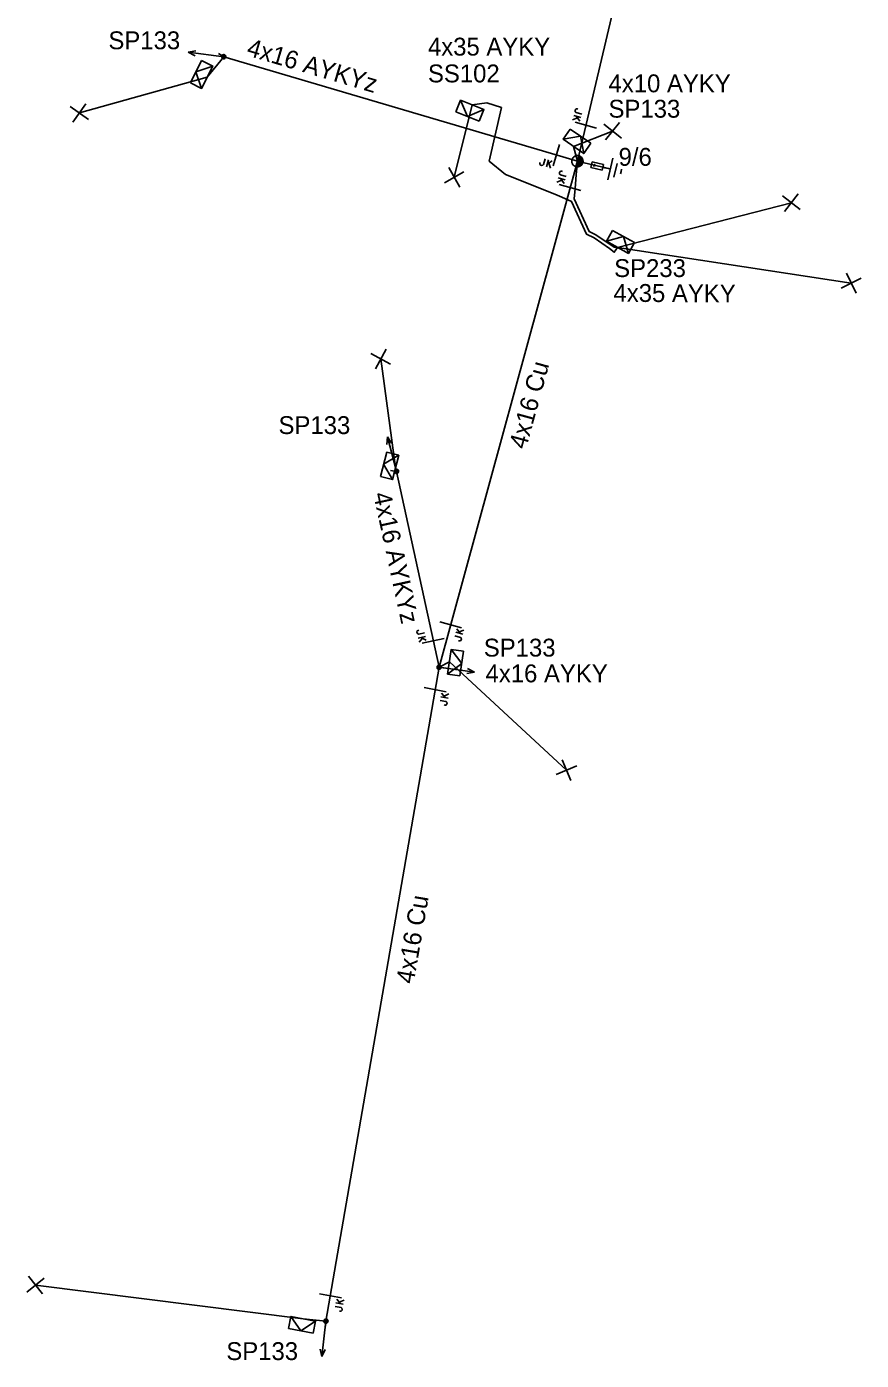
# Model space of a CAD drawing. Extents: x -788458 to -786145, y -1154772 to -1152372.
# Drawn here: x -786448.1 to -786401.4, y -1153622.8 to -1153548.2 of the extents above; entities that cross this region are included whole.
import ezdxf

# ---------------------------------------------------------------- set-up
doc = ezdxf.new("R2010")
doc.units = 0
for name, color, linetype in [('Vrstva 1', 7, 'Continuous'), ('Vrstva 12', 7, 'Continuous'), ('Vrstva 13', 7, 'Continuous'), ('Vrstva 14', 7, 'Continuous'), ('Vrstva 15', 7, 'Continuous'), ('Vrstva 16', 7, 'Continuous'), ('Vrstva 18', 7, 'Continuous'), ('Vrstva 2', 7, 'Continuous'), ('Vrstva 31', 7, 'Continuous'), ('Vrstva 33', 7, 'Continuous'), ('Vrstva 34', 7, 'Continuous'), ('Vrstva 4', 7, 'Continuous'), ('Vrstva 5', 7, 'Continuous'), ('Vrstva 52', 7, 'Continuous'), ('Vrstva 53', 7, 'Continuous'), ('Vrstva 54', 7, 'Continuous'), ('Vrstva 55', 7, 'Continuous'), ('Vrstva 59', 7, 'Continuous'), ('Vrstva 6', 7, 'Continuous'), ('Vrstva 9', 7, 'Continuous')]:
    doc.layers.add(name, color=color, linetype=linetype)

# ---------------------------------------------------------------- blocks, each defined once
blk = doc.blocks.new('NN440')
at = {"layer": 'Vrstva 2'}
for points in [[(0.63, 0), (0.63, 0.06), (0.62, 0.13), (0.6, 0.19), (0.58, 0.25), (0.55, 0.31), (0.51, 0.37), (0.47, 0.42), (0.42, 0.46), (0.37, 0.51), (0.32, 0.54), (0.26, 0.57), (0.2, 0.59), (0.13, 0.61), (0.07, 0.62), (0, 0.63), (-0.06, 0.62), (-0.13, 0.61), (-0.19, 0.59), (-0.26, 0.57), (-0.31, 0.54), (-0.37, 0.51), (-0.42, 0.46), (-0.47, 0.42), (-0.51, 0.37), (-0.54, 0.31), (-0.57, 0.25), (-0.6, 0.19), (-0.62, 0.13), (-0.63, 0.06), (-0.63, 0), (-0.63, -0.07), (-0.62, -0.14), (-0.6, -0.2), (-0.57, -0.26), (-0.54, -0.32), (-0.51, -0.37), (-0.47, -0.43), (-0.42, -0.47), (-0.37, -0.51), (-0.31, -0.55), (-0.26, -0.58), (-0.19, -0.6), (-0.13, -0.62), (-0.06, -0.63), (0, -0.63), (0.07, -0.63), (0.13, -0.62), (0.2, -0.6), (0.26, -0.58), (0.32, -0.55), (0.37, -0.51), (0.42, -0.47), (0.47, -0.43), (0.51, -0.37), (0.55, -0.32), (0.58, -0.26), (0.6, -0.2), (0.62, -0.14), (0.63, -0.07), (0.63, 0)], [(-0.63, 0), (0.63, 0)], [(-0.6, -0.18), (0.57, -0.18)], [(-0.51, -0.32), (0.5, -0.32)], [(-0.37, -0.47), (0.35, -0.47)]]:
    blk.add_lwpolyline(points, dxfattribs=at)
blk = doc.blocks.new('NN560')
at = {"layer": 'Vrstva 2'}
for points in [[(1.999, -0.001), (1.59, 0.141)], [(0, -0.001), (1.999, -0.001)], [(1.999, -0.001), (1.59, -0.134)]]:
    blk.add_lwpolyline(points, dxfattribs=at)
blk = doc.blocks.new('NN840')
at = {"layer": 'Vrstva 15'}
for points in [[(0.003, 0.619), (0.003, -0.631)], [(-0.745, -0.71), (-0.745, -0.66)], [(-0.73, -0.764), (-0.745, -0.71)], [(-0.538, -0.71), (-0.558, -0.764)], [(-0.538, -0.385), (-0.538, -0.71)], [(-0.332, -0.385), (-0.332, -0.798)], [(-0.332, -0.641), (-0.125, -0.385)], [(-0.263, -0.557), (-0.091, -0.798)], [(-0.657, -0.798), (-0.73, -0.764)], [(-0.627, -0.798), (-0.657, -0.798)], [(-0.558, -0.764), (-0.627, -0.798)]]:
    blk.add_lwpolyline(points, dxfattribs=at)
blk = doc.blocks.new('NN800')
at = {"layer": 'Vrstva 1'}
for points in [[(-0.442, 0.442), (0.442, -0.442)], [(-0.442, -0.442), (0.442, 0.442)]]:
    blk.add_lwpolyline(points, dxfattribs=at)
blk = doc.blocks.new('NN820')
at = {"layer": 'Vrstva 13'}
for points in [[(-0.003, 0.004), (-0.003, -1.049)], [(-0.165, -0.813), (0.165, -0.813)], [(-0.165, -1.473), (-0.165, -0.813)], [(0.165, -1.473), (-0.165, -1.473)], [(-0.003, -1.049), (-0.062, -0.926)], [(-0.003, -1.049), (0.057, -0.926)], [(-0.003, -1.473), (-0.003, -1.871)], [(0.165, -0.813), (0.165, -1.473)]]:
    blk.add_lwpolyline(points, dxfattribs=at)
blk = doc.blocks.new('NN630')
at = {"layer": 'Vrstva 9'}
for points in [[(-0.003, -0.7), (-0.703, 0)], [(-0.703, -0.7), (-0.703, 0), (0.697, 0), (0.697, -0.7)], [(-0.703, -0.7), (0.697, -0.7)], [(-0.003, -0.7), (0.697, 0)]]:
    blk.add_lwpolyline(points, dxfattribs=at)
blk = doc.blocks.new('NN810')
at = {"layer": 'Vrstva 14'}
for points in [[(0.004, -0.64), (0.004, -1.89)], [(0.629, -1.89), (-0.621, -1.89)], [(0.388, -2.2), (-0.399, -2.2)], [(0.004, -2.515), (-0.124, -2.515)], [(0.137, -2.515), (0.004, -2.515)]]:
    blk.add_lwpolyline(points, dxfattribs=at)
blk = doc.blocks.new('NN500')
at = {"layer": 'Vrstva 2'}
for points in [[(0, -0.24), (0.02, -0.23), (0.05, -0.23), (0.07, -0.22), (0.09, -0.22), (0.12, -0.2), (0.14, -0.19), (0.16, -0.18), (0.17, -0.16), (0.19, -0.14), (0.2, -0.12), (0.21, -0.1), (0.22, -0.07), (0.23, -0.05), (0.23, -0.02), (0.23, 0), (0.23, 0.02), (0.23, 0.05), (0.22, 0.07), (0.21, 0.1), (0.2, 0.12), (0.19, 0.14), (0.17, 0.16), (0.16, 0.17), (0.14, 0.19), (0.12, 0.2), (0.09, 0.21), (0.07, 0.22), (0.05, 0.23), (0.02, 0.23), (0, 0.23), (-0.03, 0.23), (-0.05, 0.23), (-0.07, 0.22), (-0.1, 0.21), (-0.12, 0.2), (-0.14, 0.19), (-0.16, 0.17), (-0.18, 0.16), (-0.19, 0.14), (-0.2, 0.12), (-0.22, 0.1), (-0.22, 0.07), (-0.23, 0.05), (-0.23, 0.02), (-0.24, 0), (-0.23, -0.02), (-0.23, -0.05), (-0.22, -0.07), (-0.22, -0.1), (-0.2, -0.12), (-0.19, -0.14), (-0.18, -0.16), (-0.16, -0.18), (-0.14, -0.19), (-0.12, -0.2), (-0.1, -0.22), (-0.07, -0.22), (-0.05, -0.23), (-0.03, -0.23), (0, -0.24)], [(0, -0.24), (0.02, -0.23), (0.05, -0.23), (0.07, -0.22), (0.09, -0.22), (0.12, -0.2), (0.14, -0.19), (0.16, -0.18), (0.17, -0.16), (0.19, -0.14), (0.2, -0.12), (0.21, -0.1), (0.22, -0.07), (0.23, -0.05), (0.23, -0.02), (0.23, 0), (0.23, 0.02), (0.23, 0.05), (0.22, 0.07), (0.21, 0.1), (0.2, 0.12), (0.19, 0.14), (0.17, 0.16), (0.16, 0.17), (0.14, 0.19), (0.12, 0.2), (0.09, 0.21), (0.07, 0.22), (0.05, 0.23), (0.02, 0.23), (0, 0.23), (-0.03, 0.23), (-0.05, 0.23), (-0.07, 0.22), (-0.1, 0.21), (-0.12, 0.2), (-0.14, 0.19), (-0.16, 0.17), (-0.18, 0.16), (-0.19, 0.14), (-0.2, 0.12), (-0.22, 0.1), (-0.22, 0.07), (-0.23, 0.05), (-0.23, 0.02), (-0.24, 0), (-0.23, -0.02), (-0.23, -0.05), (-0.22, -0.07), (-0.22, -0.1), (-0.2, -0.12), (-0.19, -0.14), (-0.18, -0.16), (-0.16, -0.18), (-0.14, -0.19), (-0.12, -0.2), (-0.1, -0.22), (-0.07, -0.22), (-0.05, -0.23), (-0.03, -0.23), (0, -0.24)], [(0, -0.21), (0.02, -0.2), (0.04, -0.2), (0.06, -0.2), (0.08, -0.19), (0.1, -0.18), (0.12, -0.17), (0.14, -0.15), (0.15, -0.14), (0.16, -0.12), (0.18, -0.1), (0.19, -0.08), (0.19, -0.06), (0.2, -0.04), (0.2, -0.02), (0.2, 0), (0.2, 0.02), (0.2, 0.04), (0.19, 0.06), (0.19, 0.08), (0.18, 0.1), (0.16, 0.12), (0.15, 0.14), (0.14, 0.15), (0.12, 0.17), (0.1, 0.18), (0.08, 0.19), (0.06, 0.19), (0.04, 0.2), (0.02, 0.2), (0, 0.2), (-0.02, 0.2), (-0.04, 0.2), (-0.06, 0.19), (-0.08, 0.19), (-0.1, 0.18), (-0.12, 0.17), (-0.14, 0.15), (-0.15, 0.14), (-0.17, 0.12), (-0.18, 0.1), (-0.19, 0.08), (-0.2, 0.06), (-0.2, 0.04), (-0.21, 0.02), (-0.21, 0), (-0.21, -0.02), (-0.2, -0.04), (-0.2, -0.06), (-0.19, -0.08), (-0.18, -0.1), (-0.17, -0.12), (-0.15, -0.14), (-0.14, -0.15), (-0.12, -0.17), (-0.1, -0.18), (-0.08, -0.19), (-0.06, -0.2), (-0.04, -0.2), (-0.02, -0.2), (0, -0.21)], [(0, -0.18), (0.02, -0.18), (0.04, -0.17), (0.05, -0.17), (0.07, -0.16), (0.09, -0.15), (0.1, -0.14), (0.12, -0.13), (0.13, -0.12), (0.14, -0.1), (0.15, -0.09), (0.16, -0.07), (0.17, -0.05), (0.17, -0.04), (0.17, -0.02), (0.17, 0), (0.17, 0.02), (0.17, 0.04), (0.17, 0.05), (0.16, 0.07), (0.15, 0.09), (0.14, 0.1), (0.13, 0.12), (0.12, 0.13), (0.1, 0.14), (0.09, 0.15), (0.07, 0.16), (0.05, 0.17), (0.04, 0.17), (0.02, 0.17), (0, 0.18), (-0.02, 0.17), (-0.04, 0.17), (-0.06, 0.17), (-0.07, 0.16), (-0.09, 0.15), (-0.1, 0.14), (-0.12, 0.13), (-0.13, 0.12), (-0.14, 0.1), (-0.15, 0.09), (-0.16, 0.07), (-0.17, 0.05), (-0.17, 0.04), (-0.18, 0.02), (-0.18, 0), (-0.18, -0.02), (-0.17, -0.04), (-0.17, -0.05), (-0.16, -0.07), (-0.15, -0.09), (-0.14, -0.1), (-0.13, -0.12), (-0.12, -0.13), (-0.1, -0.14), (-0.09, -0.15), (-0.07, -0.16), (-0.06, -0.17), (-0.04, -0.17), (-0.02, -0.18), (0, -0.18)], [(0, -0.15), (0.01, -0.15), (0.03, -0.14), (0.04, -0.14), (0.06, -0.13), (0.07, -0.13), (0.08, -0.12), (0.1, -0.11), (0.11, -0.1), (0.12, -0.09), (0.13, -0.07), (0.13, -0.06), (0.14, -0.05), (0.14, -0.03), (0.14, -0.02), (0.14, 0), (0.14, 0.01), (0.14, 0.03), (0.14, 0.04), (0.13, 0.06), (0.13, 0.07), (0.12, 0.09), (0.11, 0.1), (0.1, 0.11), (0.08, 0.12), (0.07, 0.13), (0.06, 0.13), (0.04, 0.14), (0.03, 0.14), (0.01, 0.14), (0, 0.15), (-0.02, 0.14), (-0.03, 0.14), (-0.05, 0.14), (-0.06, 0.13), (-0.07, 0.13), (-0.09, 0.12), (-0.1, 0.11), (-0.11, 0.1), (-0.12, 0.09), (-0.13, 0.07), (-0.13, 0.06), (-0.14, 0.04), (-0.14, 0.03), (-0.15, 0.01), (-0.15, 0), (-0.15, -0.02), (-0.14, -0.03), (-0.14, -0.05), (-0.13, -0.06), (-0.13, -0.07), (-0.12, -0.09), (-0.11, -0.1), (-0.1, -0.11), (-0.09, -0.12), (-0.07, -0.13), (-0.06, -0.13), (-0.05, -0.14), (-0.03, -0.14), (-0.02, -0.15), (0, -0.15)], [(0, -0.12), (0.01, -0.12), (0.02, -0.11), (0.03, -0.11), (0.05, -0.11), (0.06, -0.1), (0.07, -0.09), (0.08, -0.09), (0.09, -0.08), (0.09, -0.07), (0.1, -0.06), (0.11, -0.05), (0.11, -0.04), (0.11, -0.02), (0.11, -0.01), (0.12, 0), (0.11, 0.01), (0.11, 0.02), (0.11, 0.04), (0.11, 0.05), (0.1, 0.06), (0.09, 0.07), (0.09, 0.08), (0.08, 0.09), (0.07, 0.09), (0.06, 0.1), (0.05, 0.11), (0.03, 0.11), (0.02, 0.11), (0.01, 0.12), (0, 0.12), (-0.01, 0.12), (-0.03, 0.11), (-0.04, 0.11), (-0.05, 0.11), (-0.06, 0.1), (-0.07, 0.09), (-0.08, 0.09), (-0.09, 0.08), (-0.1, 0.07), (-0.1, 0.06), (-0.11, 0.05), (-0.11, 0.04), (-0.12, 0.02), (-0.12, 0.01), (-0.12, 0), (-0.12, -0.01), (-0.12, -0.02), (-0.11, -0.04), (-0.11, -0.05), (-0.1, -0.06), (-0.1, -0.07), (-0.09, -0.08), (-0.08, -0.09), (-0.07, -0.09), (-0.06, -0.1), (-0.05, -0.11), (-0.04, -0.11), (-0.03, -0.11), (-0.01, -0.12), (0, -0.12)], [(0, -0.09), (0.01, -0.09), (0.02, -0.09), (0.03, -0.08), (0.03, -0.08), (0.04, -0.08), (0.05, -0.07), (0.06, -0.07), (0.06, -0.06), (0.07, -0.05), (0.07, -0.04), (0.08, -0.04), (0.08, -0.03), (0.08, -0.02), (0.09, -0.01), (0.09, 0), (0.09, 0.01), (0.08, 0.02), (0.08, 0.03), (0.08, 0.03), (0.07, 0.04), (0.07, 0.05), (0.06, 0.06), (0.06, 0.06), (0.05, 0.07), (0.04, 0.07), (0.03, 0.08), (0.03, 0.08), (0.02, 0.08), (0.01, 0.09), (0, 0.09), (-0.01, 0.09), (-0.02, 0.08), (-0.03, 0.08), (-0.04, 0.08), (-0.04, 0.07), (-0.05, 0.07), (-0.06, 0.06), (-0.07, 0.06), (-0.07, 0.05), (-0.08, 0.04), (-0.08, 0.03), (-0.08, 0.03), (-0.09, 0.02), (-0.09, 0.01), (-0.09, 0), (-0.09, -0.01), (-0.09, -0.02), (-0.08, -0.03), (-0.08, -0.04), (-0.08, -0.04), (-0.07, -0.05), (-0.07, -0.06), (-0.06, -0.07), (-0.05, -0.07), (-0.04, -0.08), (-0.04, -0.08), (-0.03, -0.08), (-0.02, -0.09), (-0.01, -0.09), (0, -0.09)], [(0, -0.06), (0, -0.06), (0.01, -0.06), (0.02, -0.05), (0.02, -0.05), (0.03, -0.05), (0.03, -0.05), (0.04, -0.04), (0.04, -0.04), (0.05, -0.03), (0.05, -0.03), (0.05, -0.02), (0.05, -0.02), (0.05, -0.01), (0.06, -0.01), (0.06, 0), (0.06, 0.01), (0.05, 0.01), (0.05, 0.02), (0.05, 0.02), (0.05, 0.03), (0.05, 0.03), (0.04, 0.04), (0.04, 0.04), (0.03, 0.05), (0.03, 0.05), (0.02, 0.05), (0.02, 0.05), (0.01, 0.06), (0, 0.06), (0, 0.06), (-0.01, 0.06), (-0.01, 0.06), (-0.02, 0.05), (-0.02, 0.05), (-0.03, 0.05), (-0.03, 0.05), (-0.04, 0.04), (-0.04, 0.04), (-0.05, 0.03), (-0.05, 0.03), (-0.05, 0.02), (-0.06, 0.02), (-0.06, 0.01), (-0.06, 0.01), (-0.06, 0), (-0.06, -0.01), (-0.06, -0.01), (-0.06, -0.02), (-0.05, -0.02), (-0.05, -0.03), (-0.05, -0.03), (-0.04, -0.04), (-0.04, -0.04), (-0.03, -0.05), (-0.03, -0.05), (-0.02, -0.05), (-0.02, -0.05), (-0.01, -0.06), (-0.01, -0.06), (0, -0.06)], [(0, -0.03), (0, -0.03), (0, -0.03), (0.01, -0.03), (0.01, -0.03), (0.01, -0.02), (0.02, -0.02), (0.02, -0.02), (0.02, -0.02), (0.02, -0.02), (0.02, -0.01), (0.02, -0.01), (0.03, -0.01), (0.03, -0.01), (0.03, 0), (0.03, 0), (0.03, 0), (0.03, 0.01), (0.03, 0.01), (0.02, 0.01), (0.02, 0.01), (0.02, 0.02), (0.02, 0.02), (0.02, 0.02), (0.02, 0.02), (0.01, 0.02), (0.01, 0.02), (0.01, 0.03), (0, 0.03), (0, 0.03), (0, 0.03), (0, 0.03), (-0.01, 0.03), (-0.01, 0.03), (-0.01, 0.02), (-0.02, 0.02), (-0.02, 0.02), (-0.02, 0.02), (-0.02, 0.02), (-0.02, 0.02), (-0.03, 0.01), (-0.03, 0.01), (-0.03, 0.01), (-0.03, 0.01), (-0.03, 0), (-0.03, 0), (-0.03, 0), (-0.03, -0.01), (-0.03, -0.01), (-0.03, -0.01), (-0.03, -0.01), (-0.02, -0.02), (-0.02, -0.02), (-0.02, -0.02), (-0.02, -0.02), (-0.02, -0.02), (-0.01, -0.03), (-0.01, -0.03), (-0.01, -0.03), (0, -0.03), (0, -0.03)], [(0.23, 0), (0.7, 0)]]:
    blk.add_lwpolyline(points, dxfattribs=at)

msp = doc.modelspace()

# ---------------------------------------------------------------- linework, layer by layer
at = {"layer": 'Vrstva 1'}
for points in [[(-786408.35, -1153517.77), (-786417.32, -1153555.73)], [(-786417.32, -1153555.73), (-786425.06, -1153584.05)]]:
    msp.add_lwpolyline(points, dxfattribs=at)
at = {"layer": 'Vrstva 4'}
msp.add_lwpolyline([(-786425.06, -1153584.05), (-786431.39, -1153620.65), (-786432.659, -1153620.513)], dxfattribs=at)
at = {"layer": 'Vrstva 5'}
msp.add_lwpolyline([(-786415.08, -1153560.55), (-786415.266, -1153560.544), (-786416.279, -1153559.843), (-786416.664, -1153559.656), (-786417.493, -1153557.837), (-786417.446, -1153557.26), (-786417.383, -1153556.5), (-786417.32, -1153555.73)], dxfattribs=at)
at = {"layer": 'Vrstva 52'}
for points in [[(-786415.08, -1153560.55), (-786415.257, -1153560.822), (-786415.522, -1153560.61), (-786416.381, -1153560.017), (-786416.816, -1153559.804), (-786417.648, -1153557.981), (-786418.195, -1153557.745), (-786418.58, -1153557.58), (-786421.34, -1153556.47), (-786422.25, -1153555.72), (-786421.57, -1153552.73), (-786422.38, -1153552.46), (-786423.2, -1153552.58)], [(-786417.32, -1153555.73), (-786417.54, -1153554.9)], [(-786425.06, -1153584.05), (-786424.48, -1153583.74)]]:
    msp.add_lwpolyline(points, dxfattribs=at)
at = {"layer": 'Vrstva 54'}
for points in [[(-786417.32, -1153555.73), (-786437.11, -1153549.88), (-786438.037, -1153551.033)], [(-786425.06, -1153584.05), (-786427.44, -1153573.09), (-786427.49, -1153572.87)]]:
    msp.add_lwpolyline(points, dxfattribs=at)
at = {"layer": 'Vrstva 59'}
for points in [[(-786438.037, -1153551.033), (-786445.19, -1153553.03)], [(-786423.2, -1153552.58), (-786424.21, -1153556.63)], [(-786417.54, -1153554.9), (-786415.345, -1153554.048)], [(-786415.08, -1153560.55), (-786405.34, -1153558.05)], [(-786415.08, -1153560.55), (-786401.99, -1153562.55)], [(-786427.49, -1153572.87), (-786428.32, -1153566.79)], [(-786424.48, -1153583.74), (-786417.93, -1153589.81)], [(-786432.659, -1153620.513), (-786447.65, -1153618.63)]]:
    msp.add_lwpolyline(points, dxfattribs=at)

# ---------------------------------------------------------------- block references
at = {"layer": 'Vrstva 13'}
for p, rotation in [((-786437.11, -1153549.88), 172.96724717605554), ((-786427.44, -1153573.09), 104.86694999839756), ((-786425.06, -1153584.05), -7.803605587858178), ((-786431.39, -1153620.65), -96.79891665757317)]:
    msp.add_blockref('NN560', p, dxfattribs=dict(at, rotation=rotation))
for name, p, xscale, yscale, rotation in [('NN500', (-786437.11, -1153549.88), 0.49999999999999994, 0.5000000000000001, 147.59199997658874), ('NN440', (-786417.32, -1153555.73), 0.5, 0.5000000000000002, 74.88919163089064), ('NN500', (-786427.44, -1153573.09), 0.5000000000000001, 0.5, 170.86700005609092), ('NN500', (-786425.06, -1153584.05), 0.5000000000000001, 0.5, -9.423000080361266), ('NN500', (-786431.39, -1153620.65), 0.5000000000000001, 0.5, -96.94899999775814)]:
    msp.add_blockref(name, p, dxfattribs=dict(at, xscale=xscale, yscale=yscale, rotation=rotation))
at = {"layer": 'Vrstva 15', "rotation": 76.70480852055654}
msp.add_blockref('NN810', (-786417.32, -1153555.73), dxfattribs=at)
at = {"layer": 'Vrstva 16', "rotation": 76.70480852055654}
msp.add_blockref('NN820', (-786417.32, -1153555.73), dxfattribs=at)
at = {"layer": 'Vrstva 18'}
for p, rotation in [((-786416.842, -1153553.708), -105.11080830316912), ((-786418.505, -1153555.38), -16.46788168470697), ((-786417.721, -1153557.197), -105.28592851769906), ((-786425.381, -1153582.57), -77.74824908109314), ((-786424.411, -1153581.675), 74.71407161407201), ((-786425.278, -1153585.309), 79.30285551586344), ((-786431.145, -1153619.235), 79.30285558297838)]:
    msp.add_blockref('NN840', p, dxfattribs=dict(at, rotation=rotation))
at = {"layer": 'Vrstva 31'}
for p, rotation in [((-786438.037, -1153551.033), -116.31591392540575), ((-786423.2, -1153552.58), -21.92958786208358), ((-786417.54, -1153554.9), 145.3048464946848), ((-786415.08, -1153560.55), 150.89014447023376), ((-786427.49, -1153572.87), -104.72297501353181), ((-786424.48, -1153583.74), 81.60707481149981), ((-786432.659, -1153620.513), -10.763966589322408)]:
    msp.add_blockref('NN630', p, dxfattribs=dict(at, rotation=rotation))
at = {"layer": 'Vrstva 34'}
for p, rotation in [((-786445.19, -1153553.03), 9.023516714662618), ((-786415.345, -1153554.048), -173.81331392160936), ((-786424.21, -1153556.63), 74.66466393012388), ((-786405.34, -1153558.05), -172.41071668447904), ((-786401.99, -1153562.55), -18.71320559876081), ((-786428.32, -1153566.79), -73.3629582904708), ((-786417.93, -1153589.81), 157.39792785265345), ((-786447.65, -1153618.63), -6.357397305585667)]:
    msp.add_blockref('NN800', p, dxfattribs=dict(at, rotation=rotation))

# ---------------------------------------------------------------- texts
at = {"layer": 'Vrstva 12'}
msp.add_text('9/6', height=1, dxfattribs=at).set_placement((-786415.013, -1153555.985))
at = {"layer": 'Vrstva 2'}
msp.add_text('4x16 Cu', height=1, rotation=74.714, dxfattribs=at).set_placement((-786420.199, -1153571.895))
at = {"layer": 'Vrstva 33'}
for s, p in [('SP133', (-786443.563, -1153549.462)), ('SS102', (-786425.681, -1153551.317)), ('SP133', (-786415.576, -1153553.291)), ('SP233', (-786415.26, -1153562.212)), ('SP133', (-786434.043, -1153571)), ('SP133', (-786422.556, -1153583.454)), ('SP133', (-786436.964, -1153622.829))]:
    msp.add_text(s, height=1, dxfattribs=at).set_placement(p)
at = {"layer": 'Vrstva 53'}
msp.add_text('4x16 Cu', height=1, rotation=80.188, dxfattribs=at).set_placement((-786426.485, -1153601.809))
at = {"layer": 'Vrstva 54'}
msp.add_text('4x35 AYKY', height=1, rotation=0.009, dxfattribs=at).set_placement((-786425.681, -1153549.817))
for s, p in [('4x10 AYKY', (-786415.576, -1153551.87)), ('4x16 AYKY', (-786422.458, -1153584.895))]:
    msp.add_text(s, height=1, dxfattribs=at).set_placement(p)
at = {"layer": 'Vrstva 55'}
for rotation, p in [(343.532, (-786435.882, -1153549.793)), (282.25, (-786428.749, -1153574.356))]:
    msp.add_text('4x16 AYKYz', height=1, rotation=rotation, dxfattribs=at).set_placement(p)
at = {"layer": 'Vrstva 6'}
msp.add_text('4x35 AYKY', height=1, rotation=359.648, dxfattribs=at).set_placement((-786415.302, -1153563.594))

doc.saveas('drawing.dxf')
